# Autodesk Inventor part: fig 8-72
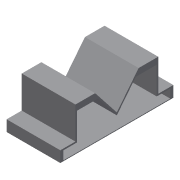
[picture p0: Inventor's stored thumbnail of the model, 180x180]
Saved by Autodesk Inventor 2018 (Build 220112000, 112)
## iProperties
Shininess: 77.0
Length Units: 11269
Angle Units: 11279
Time Units: 11290
Mass Units: 11283
Length Display Precision: 3
Angle Display Precision: 2
Created: 2002-01
Part Number: fig 8-72
Document SubType Name: Modeling
Designer: ***
Density: 1 g/cm^3
Material: Generic
Appearance: Default
Density: 0.0
Volumn: 0.0
Area: 0.0
PropertySet Name: Model Information
Control State: 0
Master: False
Checked Out: False
Author: ***
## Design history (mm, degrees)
node "Sketch1"
sketch "Sketch2"
  geometry: L1 (0, 0)-(-14.184, 17.961); L2 (-14.184, 17.961)-(-26.987, 17.961); L3 (-26.987, 17.961)-(-26.987, -2.947); L4 (-26.987, -2.947)-(-36.842, -2.947); L5 (-36.842, -2.947)-(-36.842, -10.132); L6 (26.987, 17.961)-(26.987, -2.947); L7 (14.184, 17.961)-(26.987, 17.961); L8 (26.987, -2.947)-(36.842, -2.947); L9 (36.842, -10.132)-(-36.842, -10.132); L10 (36.842, -2.947)-(36.842, -10.132); L11 (0, 0)-(14.184, 17.961)
  constraints: 22 end point, 2 horizontal, 2 parallel, 1 perpendicular
extrude "Extrusion1" new body sketch "Sketch2" distance "d0" = 35; taper "d1" = 0 deg
shell "Shell3" dims "d8" = 4, "d9" = 4, "d10" = 2, "d11" = 2, "d12" = 0.5, "d13" = 1
body "Solid1"
